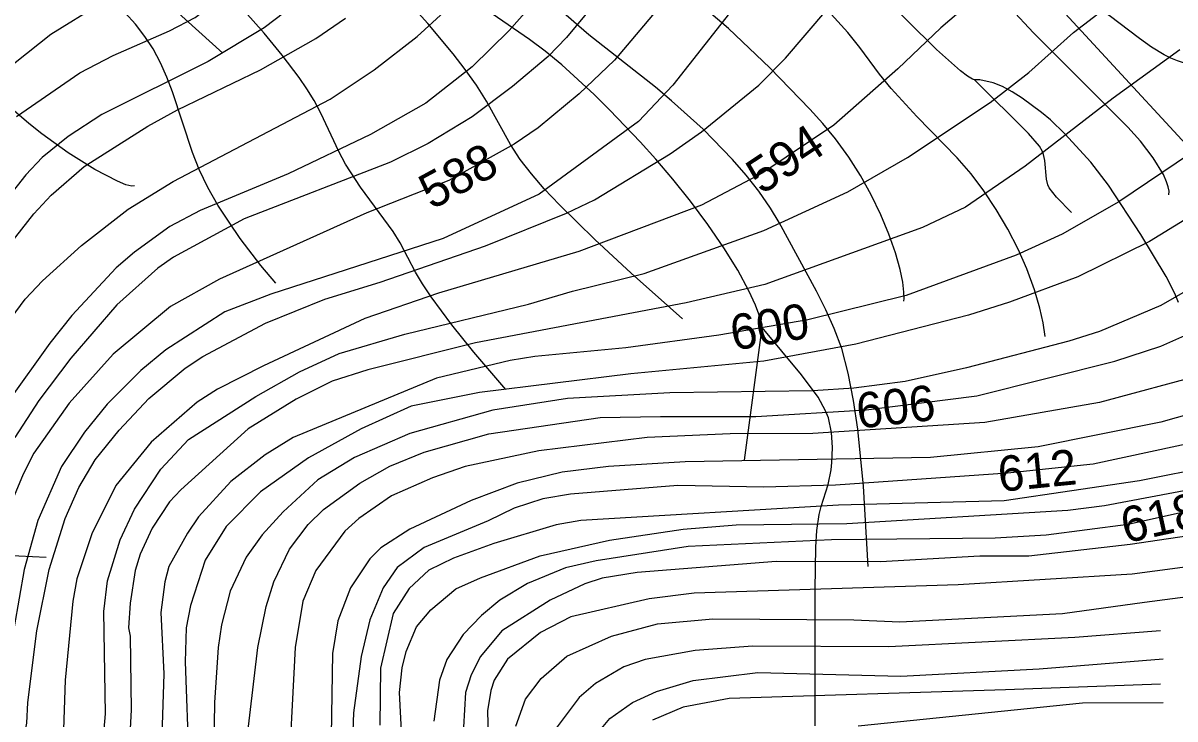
# Model space of a CAD drawing. Extents: x -709584 to -702006, y -1161789 to -1157496.
# Drawn here: x -708901 to -708575.3, y -1160607.6 to -1160411 of the extents above; entities that cross this region are included whole.
import ezdxf

# ---------------------------------------------------------------- set-up
doc = ezdxf.new("R2010")
doc.units = 0
for name, color, linetype in [('120_vrstevnice hlavní', 7, 'Continuous'), ('121_vrstevnice hlavní_popis', 7, 'Continuous'), ('122_vrstevnice základní', 7, 'Continuous'), ('411_akumulovaný odtok', 7, 'Continuous')]:
    doc.layers.add(name, color=color, linetype=linetype)

msp = doc.modelspace()

# ---------------------------------------------------------------- linework, layer by layer
at = {"layer": '120_vrstevnice hlavní'}
for points in [[(-708568.43, -1160302.92), (-708584.19, -1160310.06), (-708618.62, -1160327.28), (-708633.37, -1160336.1), (-708650.44, -1160349.12), (-708661.14, -1160359.24), (-708674.01, -1160372.98), (-708691.95, -1160395.26), (-708699.18, -1160405.53), (-708717.26, -1160428.53), (-708726.95, -1160438.8), (-708755.02, -1160459.33), (-708782.24, -1160471.81), (-708830.95, -1160487.54), (-708843.97, -1160492.6), (-708860.6, -1160503.31), (-708867.69, -1160509.09), (-708877.24, -1160518.64), (-708883.6, -1160526.59), (-708890.11, -1160536.29), (-708896.77, -1160551.47), (-708900.67, -1160565.36), (-708906.31, -1160597.76)], [(-708909.93, -1160480.02), (-708897.92, -1160464.83), (-708893.01, -1160459.62), (-708883.75, -1160451.53), (-708865.67, -1160440.1), (-708857.28, -1160435.47), (-708833.85, -1160424.19), (-708818.23, -1160415.36), (-708809.83, -1160409.58)], [(-708554.97, -1160437.06), (-708591.13, -1160461.51), (-708607.19, -1160470.62), (-708620.21, -1160476.55), (-708651.31, -1160487.98), (-708679.08, -1160494.77), (-708704.25, -1160499.11), (-708730.57, -1160502.73), (-708756.32, -1160505.19), (-708763.26, -1160506.34), (-708784.09, -1160511.26), (-708824.59, -1160528.04), (-708832.54, -1160532.96), (-708842.23, -1160540.48), (-708851.35, -1160550.46), (-708854.53, -1160555.09), (-708859.74, -1160564.49), (-708860.9, -1160568.83), (-708862.05, -1160577.51), (-708861.18, -1160594.87), (-708862.05, -1160620.9)], [(-708331.93, -1160511.84), (-708351.6, -1160514.45), (-708366.36, -1160514.73), (-708405.7, -1160517.05), (-708420.45, -1160518.5), (-708440.12, -1160521.68), (-708459.8, -1160526.16), (-708478.31, -1160531.95), (-708502.32, -1160538.31), (-708531.83, -1160547.14), (-708566.25, -1160555.09), (-708587.93, -1160558.27), (-708616.59, -1160561.6), (-708630.48, -1160561.6), (-708658.54, -1160563.19), (-708688.05, -1160563.05), (-708727.39, -1160566.23), (-708737.22, -1160567.82), (-708742.14, -1160569.41), (-708751.98, -1160574.04), (-708765.57, -1160582.72)], [(-708548.9, -1160515.17), (-708579.27, -1160523.7), (-708613.99, -1160530.65), (-708644.36, -1160533.68), (-708713.79, -1160534.98), (-708735.49, -1160536.29), (-708748.51, -1160537.88), (-708761.23, -1160540.92), (-708774.25, -1160545.83), (-708791.61, -1160553.93), (-708799.85, -1160559.28), (-708802.89, -1160562.32), (-708808.39, -1160570.57), (-708812.01, -1160579.82), (-708813.45, -1160589.08), (-708813.89, -1160612.23)], [(-708765.57, -1160582.72), (-708771.65, -1160589.95), (-708774.25, -1160595.16), (-708775.84, -1160600.07), (-708776.42, -1160609.91)], [(-708579.35, -1160597.77), (-708623.24, -1160599.35), (-708701.35, -1160601.81), (-708714.37, -1160604.27), (-708723.05, -1160607.89)]]:
    msp.add_lwpolyline(points, dxfattribs=at)
at = {"layer": '122_vrstevnice základní'}
for points in [[(-708740.41, -1160213.01), (-708742, -1160219.66), (-708748.36, -1160231.81), (-708761.23, -1160251.48), (-708766.88, -1160258.43), (-708791.61, -1160294.44), (-708821.84, -1160346.66), (-708838.04, -1160370.38), (-708847.73, -1160381.52), (-708857.57, -1160389.76), (-708879.12, -1160405.53), (-708893.15, -1160414.21), (-708910.22, -1160427.66)], [(-708902.84, -1160437.35), (-708884.91, -1160425.05), (-708875.5, -1160420.14), (-708859.59, -1160413.19), (-708852.36, -1160409.43), (-708833.99, -1160395.26), (-708825.17, -1160386.87), (-708813.89, -1160372.98), (-708795.08, -1160343.77), (-708785.68, -1160327.85), (-708776.57, -1160313.68), (-708770.93, -1160305.29), (-708765.86, -1160299.07), (-708757.62, -1160286.49), (-708749.37, -1160275.2), (-708738.38, -1160261.9), (-708722.04, -1160240.2), (-708719, -1160234.99), (-708712.92, -1160221.97), (-708711.77, -1160216.77)], [(-708685.01, -1160224), (-708684.43, -1160226.31), (-708684.14, -1160236.58), (-708685.73, -1160241.21), (-708689.35, -1160247.43), (-708714.08, -1160273.61), (-708753.71, -1160314.11), (-708766.44, -1160331.18), (-708799.85, -1160378.48), (-708812.58, -1160394.53), (-708821.12, -1160403.36), (-708832.83, -1160412.33), (-708848.6, -1160421.87), (-708878.69, -1160436.77), (-708888.23, -1160442.99), (-708895.61, -1160448.92), (-708900.24, -1160453.84), (-708916, -1160473.8)], [(-708571.32, -1160283.88), (-708577.54, -1160289.38), (-708585.64, -1160295.31), (-708603.14, -1160306.16), (-708643.49, -1160328.14), (-708658.1, -1160337.69), (-708669.53, -1160347.09), (-708681.54, -1160358.81), (-708692.82, -1160372.98), (-708733.75, -1160421.44), (-708743.73, -1160430.99), (-708755.3, -1160440.53), (-708762.1, -1160445.16), (-708780.62, -1160455.43), (-708803.76, -1160464.54), (-708845.42, -1160483.35), (-708859.3, -1160491.01), (-708875.5, -1160504.47), (-708887.94, -1160518.35), (-708897.92, -1160532.53), (-708900.96, -1160538.46), (-708907.47, -1160554.08)], [(-708885.2, -1160542.22), (-708880.57, -1160534.41), (-708873.77, -1160526.02), (-708865.38, -1160517.05), (-708855.11, -1160508.51), (-708850.19, -1160505.19), (-708832.4, -1160495.79), (-708815.62, -1160488.99), (-708800, -1160484.21), (-708770.2, -1160473.95), (-708747.35, -1160464.69), (-708739.39, -1160460.93), (-708717.99, -1160447.91), (-708709.16, -1160441.69), (-708692.96, -1160428.53), (-708685.44, -1160420.86), (-708673.73, -1160407.26), (-708653.91, -1160386.44), (-708626.14, -1160363.15), (-708604.58, -1160348.25), (-708576.81, -1160332.05), (-708540.22, -1160308.04)], [(-708536.46, -1160338.27), (-708592.58, -1160373.71), (-708602.99, -1160381.81), (-708614.28, -1160389.04), (-708641.47, -1160412.33), (-708653.62, -1160423.9), (-708671.7, -1160439.81), (-708691.81, -1160453.26), (-708709.16, -1160462.37), (-708743.88, -1160475.54), (-708783.51, -1160487.25), (-708804.34, -1160494.48), (-708832.98, -1160507.79), (-708846, -1160514.45), (-708851.78, -1160518.06), (-708864.8, -1160529.34), (-708874.78, -1160541.64), (-708881.58, -1160555.24), (-708885.77, -1160567.96), (-708886.93, -1160574.33), (-708889.1, -1160596.6), (-708889.97, -1160621.77)], [(-708710.32, -1160370.38), (-708747.35, -1160415.07), (-708752.54, -1160420.37), (-708762.62, -1160428.93), (-708773.96, -1160437.49), (-708786.4, -1160445.02), (-708797.11, -1160450.22), (-708838.48, -1160466.28), (-708858.44, -1160477.13), (-708862.92, -1160480.17), (-708874.49, -1160490.58), (-708887.51, -1160505.62), (-708896.48, -1160517.63), (-708903.28, -1160528.04)], [(-708877.67, -1160606.15), (-708878.11, -1160577.22), (-708877.09, -1160568.54), (-708873.48, -1160556.97), (-708869.43, -1160548.29), (-708862.05, -1160537.01), (-708854.24, -1160528.62), (-708835.15, -1160516.47), (-708822.85, -1160509.53), (-708811.57, -1160504.32), (-708793.06, -1160498.82), (-708758.05, -1160490.43), (-708745.61, -1160486.67), (-708725.36, -1160481.76), (-708691.52, -1160469.61), (-708667.8, -1160458.61), (-708650.87, -1160448.92), (-708627.58, -1160433.44), (-708616.59, -1160424.91), (-708604.01, -1160413.63), (-708591.42, -1160403.94), (-708558.73, -1160383.11)], [(-708914.99, -1160508.66), (-708900.38, -1160488.99), (-708895.46, -1160483.78), (-708884.47, -1160473.8), (-708871.31, -1160463.53), (-708858.58, -1160455.72), (-708814.18, -1160432.43), (-708801.73, -1160424.19), (-708789.58, -1160414.78), (-708774.25, -1160400.75)], [(-708752.56, -1160400.61), (-708763.55, -1160413.05), (-708773.96, -1160423.32), (-708787.12, -1160433.61), (-708802.75, -1160442.41), (-708826.04, -1160453.55), (-708850.91, -1160463.96), (-708859.45, -1160468.45), (-708869.43, -1160475.68), (-708874.64, -1160480.16), (-708887.22, -1160493.62), (-708893.44, -1160501.43), (-708905.01, -1160517.63)], [(-708573.87, -1160418.5), (-708592.72, -1160432.14), (-708617.6, -1160451.38), (-708634.53, -1160462.95), (-708646.68, -1160468.74), (-708691.23, -1160484.79), (-708713.5, -1160490), (-708773.1, -1160501.28), (-708803.47, -1160508.95), (-708813.6, -1160512.13), (-708823.72, -1160517.19), (-708837.32, -1160525.58), (-708856.41, -1160542.8), (-708859.59, -1160546.27), (-708864.51, -1160553.64), (-708867.84, -1160561.02), (-708869.28, -1160565.65), (-708870.73, -1160574.91), (-708871.17, -1160581.85), (-708870.73, -1160584.16), (-708870.44, -1160604.99), (-708871.31, -1160621.19)], [(-708565.39, -1160462.23), (-708582.45, -1160472.64), (-708602.71, -1160482.62), (-708622.09, -1160489.86), (-708633.66, -1160493.47), (-708665.48, -1160501.72), (-708691.52, -1160506.49), (-708729.12, -1160510.11), (-708771.94, -1160515.31), (-708791.23, -1160519.22), (-708805.35, -1160525.58), (-708820.25, -1160533.83), (-708833.85, -1160543.37), (-708843.54, -1160553.21), (-708849.47, -1160562.76), (-708853.66, -1160575.49), (-708854.82, -1160581.85), (-708855.11, -1160591.4), (-708854.1, -1160620.04)], [(-708564.81, -1160482.48), (-708579.27, -1160490.72), (-708596.63, -1160498.1), (-708605.31, -1160500.85), (-708634.24, -1160508.37), (-708651.59, -1160512.28), (-708666.06, -1160514.16), (-708677.63, -1160514.88), (-708718.13, -1160515.46), (-708747.06, -1160517.05), (-708768.18, -1160520.38), (-708791.61, -1160526.89), (-708807.23, -1160533.68), (-708817.65, -1160540.05), (-708827.48, -1160549.02), (-708833.41, -1160555.52), (-708837.9, -1160561.89), (-708842.38, -1160571.44), (-708844.84, -1160580.98), (-708845.85, -1160587.35), (-708846.86, -1160602.97), (-708847.15, -1160621.19)], [(-708324.7, -1160486.67), (-708336.27, -1160492.89), (-708344.95, -1160495.93), (-708399.91, -1160505.48), (-708417.27, -1160507.79), (-708434.63, -1160510.97), (-708460.66, -1160518.21), (-708510.42, -1160534.7), (-708536.46, -1160541.06), (-708588.53, -1160552.63), (-708611.67, -1160555.67), (-708626.14, -1160556.54), (-708672.42, -1160556.97), (-708712.92, -1160558.85), (-708738.96, -1160562.9), (-708747.64, -1160564.93), (-708758.34, -1160569.27), (-708766.15, -1160574.04), (-708771.36, -1160578.38), (-708776.57, -1160583.73), (-708781.2, -1160590.82), (-708783.22, -1160596.6), (-708784.81, -1160608.18)], [(-708793.2, -1160625.53), (-708794.5, -1160600.07), (-708793.78, -1160593.13), (-708792.62, -1160588.5), (-708789.73, -1160581.56), (-708785.68, -1160576.79), (-708778.59, -1160570.86), (-708771.65, -1160567.67), (-708754.73, -1160561.45), (-708735.2, -1160557.11), (-708714.37, -1160553.93), (-708699.33, -1160552.78), (-708668.08, -1160552.34), (-708605.6, -1160548.58), (-708595.18, -1160547.28), (-708569.15, -1160542.36), (-708517.08, -1160529.92), (-708462.98, -1160511.55), (-708402.81, -1160495.35), (-708379.37, -1160491.01)], [(-708840.35, -1160635.95), (-708834.57, -1160587.35), (-708832.26, -1160575.78), (-708830.09, -1160568.83), (-708825.6, -1160559.57), (-708820.39, -1160552.63), (-708816.06, -1160548.44), (-708805.79, -1160540.92), (-708797.25, -1160536.14), (-708787.56, -1160532.24), (-708769.33, -1160527.03), (-708737.8, -1160522.4), (-708720.73, -1160522.11), (-708693.83, -1160522.11), (-708662.59, -1160520.23), (-708631.34, -1160516.32), (-708592.29, -1160506.49), (-708579.27, -1160502.29), (-708567.41, -1160496.94)], [(-708566.54, -1160510.11), (-708596.63, -1160518.21), (-708629.03, -1160523.85), (-708677.63, -1160526.89), (-708701.06, -1160527.03), (-708724.5, -1160528.04), (-708755.16, -1160531.8), (-708775.99, -1160536.29), (-708785.25, -1160539.47), (-708796.82, -1160544.53), (-708806.08, -1160550.9), (-708809.98, -1160554.51), (-708818.23, -1160565.65), (-708821.84, -1160574.33), (-708824.01, -1160587.35), (-708826.18, -1160629)], [(-708565.96, -1160528.62), (-708598.37, -1160535.56), (-708622.67, -1160538.17), (-708671.27, -1160541.49), (-708691.52, -1160542.07), (-708715.82, -1160541.64), (-708746.19, -1160544.1), (-708754, -1160545.4), (-708762.1, -1160548), (-708769.48, -1160551.62), (-708787.56, -1160559.14), (-708795.23, -1160564.78), (-708799.13, -1160570.57), (-708802.91, -1160579.62), (-708805.43, -1160589.89), (-708807.52, -1160605.86), (-708808.68, -1160637.1)], [(-708564.52, -1160536.14), (-708585.35, -1160540.34), (-708623.53, -1160545.98), (-708670.4, -1160547.14), (-708743.3, -1160551.47), (-708750.24, -1160552.78), (-708767.89, -1160557.98), (-708779.23, -1160562.14), (-708786.29, -1160565.57), (-708791.84, -1160570.71), (-708796.37, -1160577.8), (-708799.9, -1160593.21), (-708800.14, -1160609.33)], [(-708905.16, -1160634.79), (-708899.95, -1160608.75), (-708899.66, -1160602.97), (-708897.06, -1160582.72), (-708893.58, -1160565.36), (-708889.1, -1160550.9), (-708885.2, -1160542.22)], [(-708546.1, -1160561.18), (-708587.37, -1160566.66), (-708636.55, -1160569.7), (-708711.19, -1160572.01), (-708723.92, -1160573.6), (-708746.06, -1160578.74), (-708754.64, -1160583.15), (-708763.96, -1160590.73), (-708767.74, -1160596.6), (-708768.76, -1160599.5), (-708769.62, -1160605.28), (-708768.76, -1160641.73)], [(-708761.67, -1160609.62), (-708758.92, -1160601.96), (-708754.52, -1160596.18), (-708747.21, -1160589.82), (-708734.62, -1160584.16), (-708721.6, -1160580.69), (-708705.98, -1160579.25), (-708666.06, -1160579.53), (-708653.04, -1160580.11), (-708607.04, -1160577.8), (-708583.9, -1160574.62), (-708546.51, -1160569.68)], [(-708579.35, -1160582.72), (-708603.57, -1160584.6), (-708656.22, -1160587.2), (-708694.7, -1160587.06), (-708710.9, -1160588.21), (-708725.07, -1160590.82), (-708731.15, -1160592.84), (-708739.1, -1160597.61), (-708743.73, -1160601.52), (-708750.22, -1160610.21)], [(-708738.82, -1160611.94), (-708735.05, -1160607.45), (-708728.69, -1160602.97), (-708721.89, -1160599.78), (-708711.48, -1160596.75), (-708693.25, -1160594.43), (-708652.75, -1160595.45), (-708613.7, -1160593.42), (-708578.6, -1160590.62)], [(-708578.6, -1160603.04), (-708601.44, -1160603.15), (-708664.9, -1160609.62)], [(-708914.7, -1160710.58), (-708897.63, -1160676.74), (-708893.01, -1160666.32), (-708882.88, -1160637.68), (-708880.28, -1160626.4), (-708878.4, -1160614.83), (-708877.67, -1160606.15)]]:
    msp.add_lwpolyline(points, dxfattribs=at)
at = {"layer": '411_akumulovaný odtok'}
for p, q in [((-708844.49, -1160419.5), (-708896.99, -1160372)), ((-708696.99, -1160534.5), (-708691.99, -1160497))]:
    msp.add_line(p, q, dxfattribs=at)
for points in [[(-708829.49, -1160484.5), (-708833.73, -1160479.45), (-708839.55, -1160471.82), (-708842.75, -1160467.24), (-708845.88, -1160462.37), (-708848.73, -1160457.38), (-708851.18, -1160452.3), (-708853.08, -1160447.55), (-708858.74, -1160430.38), (-708860.33, -1160426.21), (-708862.12, -1160422.17), (-708864.2, -1160418.29), (-708866.57, -1160414.72), (-708869.22, -1160411.32), (-708875.06, -1160404.83), (-708881.32, -1160398.58), (-708887.76, -1160392.44), (-708913.97, -1160368.14), (-708927.22, -1160356.21), (-708934.04, -1160350.51), (-708941.04, -1160345.36), (-708949.12, -1160340.25), (-708963.77, -1160331.89), (-708981.99, -1160322)], [(-708576.99, -1160459.5), (-708576.95, -1160458.42), (-708577.18, -1160457.28), (-708577.63, -1160455.84), (-708578.54, -1160453.76), (-708581.4, -1160449.08), (-708585.03, -1160444.36), (-708588.65, -1160440.34), (-708615.32, -1160413.68), (-708621.74, -1160406.79), (-708629.17, -1160397.52), (-708651.99, -1160367)], [(-708714.49, -1160494.5), (-708729.01, -1160481.61), (-708739.29, -1160472.15), (-708749.33, -1160462.35), (-708753.67, -1160457.76), (-708757.26, -1160453.59), (-708760.38, -1160449.5), (-708763.19, -1160445.27), (-708769.9, -1160433.05), (-708772.78, -1160428.51), (-708775.95, -1160424.06), (-708779.33, -1160419.69), (-708786.51, -1160411.1), (-708797.85, -1160398.43)], [(-708764.49, -1160514.5), (-708773.48, -1160503.92), (-708779.7, -1160496.2), (-708785.61, -1160488.29), (-708788.05, -1160484.63), (-708789.99, -1160481.34), (-708794.32, -1160473.03), (-708796.35, -1160469.81), (-708805.56, -1160457.3), (-708809.85, -1160450.79), (-708811.72, -1160447.28), (-708816.83, -1160436.43), (-708818.69, -1160432.89), (-708820.72, -1160429.55), (-708822.94, -1160426.31), (-708827.73, -1160420.01), (-708832.83, -1160413.86), (-708846.14, -1160398.85)], [(-708691.99, -1160497), (-708692.04, -1160496.15), (-708692.69, -1160493.97), (-708693.93, -1160490.7), (-708695.79, -1160486.59), (-708698.92, -1160480.81), (-708702.86, -1160474.47), (-708707.39, -1160467.88), (-708712.27, -1160461.32), (-708717.25, -1160455.06), (-708722.05, -1160449.38), (-708726.46, -1160444.52), (-708735.09, -1160435.53), (-708739.5, -1160431.16), (-708748.62, -1160422.8), (-708753.39, -1160418.9), (-708757.81, -1160415.63), (-708775.92, -1160403.13)], [(-708631.99, -1160427), (-708632.57, -1160426.84), (-708633.92, -1160425.98), (-708635.91, -1160424.48), (-708642.7, -1160418.44), (-708659.27, -1160401.94)], [(-708521.99, -1160462), (-708543.29, -1160436.8), (-708547.77, -1160432.14), (-708551, -1160429.45), (-708552.75, -1160428.32), (-708556.43, -1160426.67), (-708560.38, -1160425.46), (-708570.56, -1160422.93), (-708574.54, -1160421.68), (-708576.46, -1160420.9), (-708578.32, -1160419.98), (-708581.89, -1160417.81), (-708585.33, -1160415.37), (-708593.89, -1160408.84), (-708598.28, -1160406.05), (-708603.09, -1160403.71), (-708605.43, -1160402.88), (-708609.26, -1160402.07), (-708611.99, -1160402)], [(-708506.99, -1160569.5), (-708508.45, -1160549.26), (-708509.5, -1160538.59), (-708510.17, -1160533.61), (-708510.93, -1160529.2), (-708511.85, -1160525.38), (-708513.01, -1160521.71), (-708514.51, -1160518.19), (-708516.3, -1160515.02), (-708518.37, -1160511.98), (-708520.64, -1160509.03), (-708533, -1160494.74), (-708537.64, -1160488.85), (-708539.72, -1160485.78), (-708541.73, -1160482.39), (-708547.39, -1160472.16), (-708549.54, -1160468.98), (-708551.75, -1160466.31), (-708573.3, -1160443.91), (-708611.99, -1160402)], [(-708661.99, -1160564.5), (-708663.37, -1160541.84), (-708664.98, -1160525.74), (-708666.16, -1160517.6), (-708667.65, -1160509.89), (-708669.5, -1160502.94), (-708671.61, -1160497.28), (-708674, -1160491.98), (-708676.6, -1160486.76), (-708687.21, -1160467.31), (-708689.66, -1160463.24), (-708692.95, -1160458.49), (-708696.57, -1160453.92), (-708700.43, -1160449.48), (-708708.72, -1160440.97), (-708717.59, -1160432.92), (-708722.18, -1160429.12), (-708740.97, -1160414.32), (-708750.21, -1160406.33)], [(-708651.99, -1160489.5), (-708651.84, -1160488.82), (-708651.9, -1160486.98), (-708652.26, -1160484.16), (-708652.98, -1160480.55), (-708654.3, -1160475.86), (-708656.16, -1160470.65), (-708658.49, -1160465.14), (-708661.21, -1160459.54), (-708664.24, -1160454.04), (-708667.48, -1160448.86), (-708671.22, -1160443.66), (-708674.87, -1160439.3), (-708678.52, -1160435.3), (-708689.86, -1160423.65), (-708701.56, -1160412.54), (-708709.6, -1160405.66)], [(-708611.99, -1160499.5), (-708612.54, -1160495.7), (-708613.51, -1160491.54), (-708615.03, -1160486.34), (-708617.15, -1160480.44), (-708619.61, -1160474.86), (-708622.53, -1160469.21), (-708625.79, -1160463.66), (-708629.28, -1160458.4), (-708632.88, -1160453.6), (-708636.83, -1160449), (-708648.24, -1160437.32), (-708655.48, -1160429.45), (-708658.79, -1160425.38), (-708664.34, -1160417.88), (-708667.79, -1160413.61), (-708675.36, -1160405.33)], [(-708574.29, -1160489.87), (-708575.34, -1160487.4), (-708577.81, -1160482.55), (-708584.92, -1160470.7), (-708594.06, -1160456.77), (-708599.08, -1160450.23), (-708606.45, -1160442.27), (-708610.51, -1160438.34), (-708612.98, -1160436.24), (-708618.48, -1160432.16), (-708621.32, -1160430.39), (-708624.08, -1160428.93), (-708626.65, -1160427.87), (-708630.41, -1160426.97), (-708631.99, -1160427)], [(-708604.49, -1160464.5), (-708608.82, -1160460.2), (-708610.85, -1160457.5), (-708611.22, -1160456.69), (-708611.63, -1160455.04), (-708612.1, -1160449.78), (-708612.43, -1160448.1), (-708612.7, -1160447.3), (-708613.59, -1160445.72), (-708616.72, -1160442.14), (-708631.99, -1160427)], [(-708869.49, -1160457), (-708870.18, -1160457.08), (-708871.9, -1160456.64), (-708874.3, -1160455.68), (-708880.68, -1160452.34), (-708888.19, -1160447.61), (-708895.7, -1160442.24), (-708899.39, -1160439.34), (-708905.49, -1160434.05)], [(-708676.99, -1160609.5), (-708677.06, -1160570.99), (-708676.84, -1160559.03), (-708676.52, -1160554.33), (-708675.88, -1160549.77), (-708675.36, -1160547.57), (-708673.31, -1160541.32), (-708672.49, -1160537.22), (-708672.27, -1160535.12), (-708672.13, -1160530.86), (-708672.41, -1160526.63), (-708673.29, -1160522.54), (-708674.07, -1160520.53), (-708676.17, -1160516.7), (-708680.84, -1160510.33), (-708691.99, -1160497)], [(-708894.49, -1160562), (-708937.01, -1160559.91)]]:
    msp.add_lwpolyline(points, dxfattribs=at)

# ---------------------------------------------------------------- texts
at = {"layer": '121_vrstevnice hlavní_popis'}
for s, rotation, p in [('594', 33.3448, (-708692.15, -1160459.61)), ('588', 28.4724, (-708785.43, -1160463.83)), ('600', 9.7663, (-708700.07, -1160503.56)), ('606', 6.6491, (-708664.75, -1160525.59)), ('612', 5.7146, (-708624.85, -1160543.45)), ('618', 12.3901, (-708589.31, -1160557.99))]:
    msp.add_text(s, height=10, rotation=rotation, dxfattribs=at).set_placement(p)

doc.saveas('drawing.dxf')
